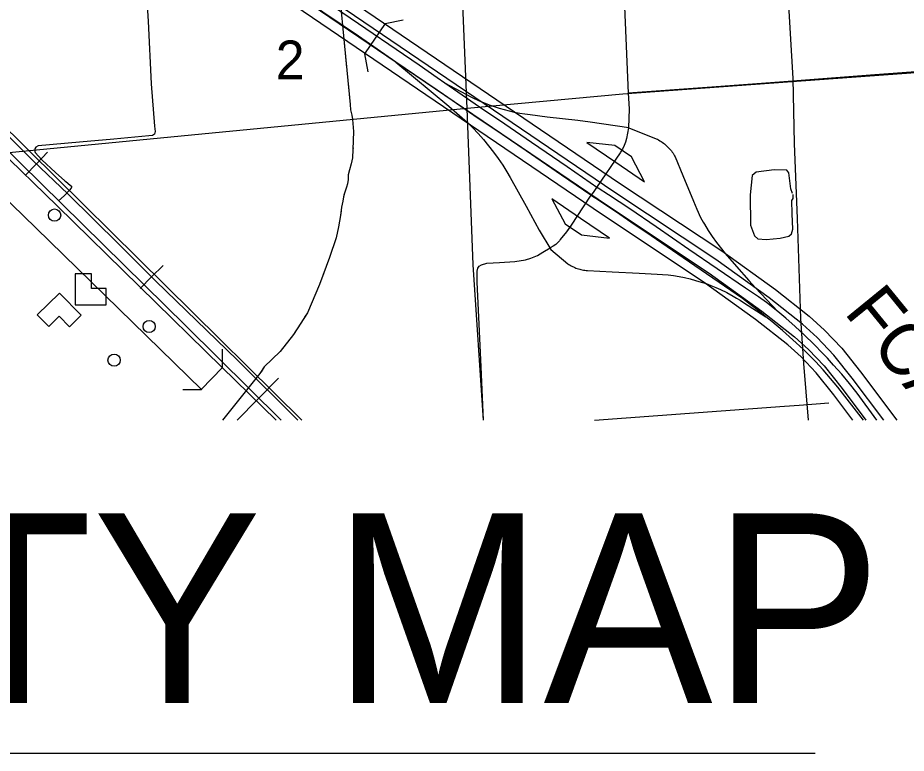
# Model space of a CAD drawing. Extents: x 646058 to 725608, y 1473014 to 1561048.
# Drawn here: x 659024 to 662655, y 1542587 to 1545593 of the extents above; entities that cross this region are included whole.
import ezdxf

# ---------------------------------------------------------------- set-up
doc = ezdxf.new("R2010")
doc.units = 0
doc.layers.add('Default', color=7, linetype='Continuous')
doc.layers.add('R_Grid', color=7, linetype='Continuous')

msp = doc.modelspace()

# ---------------------------------------------------------------- linework, layer by layer
at = {"layer": 'Default'}
for p, q in [((660525.3, 1545570.5), (660441, 1545446.5)), ((660525.3, 1545570.5), (660599, 1545584.6)), ((660441, 1545446.5), (660455.1, 1545372.8)), ((661350, 1545083.4), (661467.9, 1545003.3)), ((661464.8, 1545070.7), (661350, 1545083.4)), ((661531.8, 1545025.2), (661464.8, 1545070.7)), ((659099.7, 1544996.2), (659145.3, 1545043.8)), ((661585.8, 1544923.2), (661531.8, 1545025.2)), ((659099.7, 1544996.2), (659054.1, 1544948.5)), ((661467.9, 1545003.3), (661585.8, 1544923.2)), ((661324.4, 1544773.1), (661206.4, 1544853.2)), ((661206.4, 1544853.2), (661260.5, 1544751.2)), ((661442.3, 1544693), (661324.4, 1544773.1)), ((661260.5, 1544751.2), (661327.5, 1544705.7)), ((661327.5, 1544705.7), (661442.3, 1544693)), ((659570.6, 1544533.8), (659617.3, 1544580.4)), ((659570.6, 1544533.8), (659524, 1544487.1)), ((659860.7, 1544163.5), (659773.2, 1544074.1)), ((659816.9, 1544118.8), (659816.9, 1544118.8)), ((659920.4, 1543949.1), (660089.6, 1544119.9)), ((660043.1, 1544073), (659996.7, 1544026.1))]:
    msp.add_line(p, q, dxfattribs=at)
for points in [[(660769.4, 1545325.6), (660738.5, 1545348.4), (660663.9, 1545400), (660351.8, 1545612.7), (660082.4, 1545798.5), (659708.6, 1546052.2), (659626.2, 1546108.4), (659548.6, 1546163.6), (659466.6, 1546224.7), (659349.1, 1546318.2), (659069.3, 1546541.2), (658623.6, 1546894.9), (658241.6, 1547197.9), (657885.8, 1547482.1), (657634.2, 1547680.9), (657263.8, 1547976.9), (656828.4, 1548315.6), (656441.1, 1548622), (656095.5, 1548896.7), (656046.9, 1548935.5)], [(660769.4, 1545325.6), (660738.5, 1545348.4), (660663.9, 1545400), (660351.8, 1545612.7), (660082.4, 1545798.5), (659708.6, 1546052.2), (659626.2, 1546108.4), (659548.6, 1546163.6), (659466.6, 1546224.7), (659349.1, 1546318.2), (659069.3, 1546541.2), (658623.6, 1546894.9), (658241.6, 1547197.9), (657885.8, 1547482.1), (657634.2, 1547680.9), (657263.8, 1547976.9), (656828.4, 1548315.6), (656441.1, 1548622), (656095.5, 1548896.7), (656046.9, 1548935.5)], [(660769.4, 1545325.6), (660738.5, 1545348.4), (660663.9, 1545400), (660351.8, 1545612.7), (660082.4, 1545798.5), (659708.6, 1546052.2), (659626.2, 1546108.4), (659548.6, 1546163.6), (659466.6, 1546224.7), (659349.1, 1546318.2), (659069.3, 1546541.2), (658623.6, 1546894.9), (658241.6, 1547197.9), (657885.8, 1547482.1), (657634.2, 1547680.9), (657263.8, 1547976.9), (656828.4, 1548315.6), (656441.1, 1548622), (656095.5, 1548896.7), (656046.9, 1548935.5)], [(660769.4, 1545325.6), (660738.5, 1545348.4), (660663.9, 1545400), (660351.8, 1545612.7), (660082.4, 1545798.5), (659708.6, 1546052.2), (659626.2, 1546108.4), (659548.6, 1546163.6), (659466.6, 1546224.7), (659349.1, 1546318.2), (659069.3, 1546541.2), (658623.6, 1546894.9), (658241.6, 1547197.9), (657885.8, 1547482.1), (657634.2, 1547680.9), (657263.8, 1547976.9), (656828.4, 1548315.6), (656441.1, 1548622), (656095.5, 1548896.7), (656046.9, 1548935.5)], [(660568.9, 1545412.2), (660415.9, 1545517.6), (660049.7, 1545765.9), (659676.3, 1546020.4), (659594.4, 1546076.3), (659513.4, 1546133.5), (659434.2, 1546193.4), (659312.7, 1546288.9), (659032.8, 1546511.9), (658586.8, 1546865.8), (658204.4, 1547170.3), (657843.4, 1547456), (657618.6, 1547634.8), (657231.1, 1547944.9), (656803, 1548283.3), (656415.6, 1548589.8), (656070, 1548864.5), (656025.4, 1548900.1)], [(660568.9, 1545412.2), (660415.9, 1545517.6), (660049.7, 1545765.9), (659676.3, 1546020.4), (659594.4, 1546076.3), (659513.4, 1546133.5), (659434.2, 1546193.4), (659312.7, 1546288.9), (659032.8, 1546511.9), (658586.8, 1546865.8), (658204.4, 1547170.3), (657843.4, 1547456), (657618.6, 1547634.8), (657231.1, 1547944.9), (656803, 1548283.3), (656415.6, 1548589.8), (656070, 1548864.5), (656025.4, 1548900.1)], [(660568.9, 1545412.2), (660415.9, 1545517.6), (660049.7, 1545765.9), (659676.3, 1546020.4), (659594.4, 1546076.3), (659513.4, 1546133.5), (659434.2, 1546193.4), (659312.7, 1546288.9), (659032.8, 1546511.9), (658586.8, 1546865.8), (658204.4, 1547170.3), (657843.4, 1547456), (657618.6, 1547634.8), (657231.1, 1547944.9), (656803, 1548283.3), (656415.6, 1548589.8), (656070, 1548864.5), (656025.4, 1548900.1)], [(660568.9, 1545412.2), (660415.9, 1545517.6), (660049.7, 1545765.9), (659676.3, 1546020.4), (659594.4, 1546076.3), (659513.4, 1546133.5), (659434.2, 1546193.4), (659312.7, 1546288.9), (659032.8, 1546511.9), (658586.8, 1546865.8), (658204.4, 1547170.3), (657843.4, 1547456), (657618.6, 1547634.8), (657231.1, 1547944.9), (656803, 1548283.3), (656415.6, 1548589.8), (656070, 1548864.5), (656025.4, 1548900.1)], [(662436.8, 1543949.1), (662359.4, 1544051.8), (662287.7, 1544142), (662226.2, 1544206.7), (662171.1, 1544256.2), (662039.6, 1544360.1), (661825.6, 1544514.5), (661409.9, 1544790.1), (660156.2, 1545642.2), (659402.5, 1546176), (659168.3, 1546365.6), (656047.6, 1548854.7)], [(656121.8, 1548850.2), (659194.9, 1546398.7), (659428.2, 1546209.9), (660180.5, 1545677.1), (661433.6, 1544825.4), (661849.8, 1544549.5), (662065.2, 1544394), (662198.5, 1544288.7), (662255.8, 1544237.2), (662319.7, 1544169.9), (662393, 1544077.8), (662490.1, 1543949.1)], [(662563.6, 1543949.1), (662434.9, 1544119.8), (662359.3, 1544214.8), (662291.6, 1544286.1), (662230.9, 1544340.6), (662094.9, 1544448), (661877.3, 1544605.1), (661459.5, 1544882.1), (660209, 1545732), (659458.9, 1546263.3), (659227.1, 1546450.9), (656233.5, 1548837.4)], [(656290.3, 1548854.7), (659253.7, 1546484), (659484.6, 1546297.2), (660233.2, 1545766.9), (661483.2, 1544917.4)], [(660168.2, 1543949.1), (659919.8, 1544195.1), (659588.3, 1544516.1), (659439.9, 1544664.5), (659227.9, 1544873.5), (659088.6, 1545006.7), (658890.3, 1545205.1), (658596.6, 1545494.3), (658384.6, 1545703.3), (658109.1, 1545971.3), (657900.1, 1546177.3), (657753.3, 1546321.1), (657536.8, 1546533.1), (657293, 1546773.9), (657050.8, 1547016.2), (656776.7, 1547278.1), (656548.1, 1547505.3), (656345.2, 1547702.1), (656118.1, 1547924.7), (656003.1, 1548039), (655996.2, 1548045.9), (655880.4, 1548161), (655686.6, 1548351.8)], [(661399.3, 1548081), (661396.5, 1548033.7), (661404.3, 1547874.9), (661421.1, 1547585.4), (661435.5, 1547270.9), (661451.2, 1546917.6), (661467.5, 1546563.1), (661481.5, 1546210.5), (661490.7, 1545982.8), (661504, 1545638), (661518.1, 1545284.8)], [(661399.3, 1548081), (661396.5, 1548033.7), (661404.3, 1547874.9), (661421.1, 1547585.4), (661435.5, 1547270.9), (661451.2, 1546917.6), (661467.5, 1546563.1), (661481.5, 1546210.5), (661490.7, 1545982.8), (661504, 1545638), (661518.1, 1545284.8)], [(660168.2, 1543949.1), (659919.8, 1544195.1), (659588.3, 1544516.1), (659439.9, 1544664.5), (659227.9, 1544873.5), (659088.6, 1545006.7), (658890.3, 1545205.1), (658596.6, 1545494.3), (658384.6, 1545703.3), (658109.1, 1545971.3), (657900.1, 1546177.3), (657753.3, 1546321.1), (657536.8, 1546533.1), (657293, 1546773.9), (657050.8, 1547016.2), (656776.7, 1547278.1), (656548.1, 1547505.3), (656345.2, 1547702.1), (656118.1, 1547924.7), (656003.1, 1548039)], [(660860.6, 1545222), (660771.9, 1547344.4), (660739.4, 1548040.9)], [(656425.6, 1547675.7), (657430.5, 1546682.8), (658072.2, 1546037.3), (659069.6, 1545049.8)], [(657050.8, 1547016.2), (657293, 1546773.9), (657536.8, 1546533.1), (657753.3, 1546321.1), (657900.1, 1546177.3), (658109.1, 1545971.3), (658384.6, 1545703.3), (658596.6, 1545494.3), (658890.3, 1545205.1), (659088.6, 1545006.7), (659227.9, 1544873.5), (659439.9, 1544664.5), (659588.3, 1544516.1), (659919.8, 1544195.1), (660168.2, 1543949.1)], [(662537, 1546981.5), (662383.9, 1546835.7), (662315.8, 1546767.6), (662283.9, 1546720.8), (662225.4, 1546615.5), (662154.2, 1546481.5), (662139.3, 1546437.9), (662149.9, 1546231.5), (662169.1, 1545738), (662191.4, 1545345.5), (662196.7, 1545079.5), (662209.8, 1544772.2), (662223.4, 1544363.7)], [(656984.6, 1546977.7), (657726.5, 1546250.4), (657872.6, 1546102.8), (658101.1, 1545883.7), (658939.4, 1545061.8), (659185.2, 1544824.5), (659858.4, 1544165.7)], [(659775.5, 1544072), (659098.1, 1544734.9), (658852.2, 1544972.2), (658014.1, 1545794), (657784.9, 1546013.7), (657638.3, 1546161.8), (656924.6, 1546861.4)], [(659538, 1545854.2), (659544.3, 1545769.8), (659556, 1545579.2), (659569.5, 1545323.1), (659582.9, 1545149.7), (659584.7, 1545128.1), (659582.9, 1545117.3), (659574.8, 1545111.9), (659559.6, 1545110.1), (659415.8, 1545097.5), (659276.5, 1545084.9), (659106.7, 1545069.7), (659096.9, 1545063.8), (659093.3, 1545056.9), (659093.3, 1545048.5), (659093.7, 1545046.5)], [(660332.6, 1545762.5), (660359.6, 1545477.6), (660381.7, 1545239.3), (660384.1, 1545217.2), (660389, 1545195.1), (660391.5, 1545177.9), (660396.4, 1545128.8), (660393.9, 1545055.1), (660391.5, 1545020.7), (660386.6, 1544996.2), (660379.2, 1544971.6), (660374.3, 1544951.9), (660374.3, 1544932.3), (660371.8, 1544915.1), (660366.9, 1544900.4), (660359.6, 1544875.8), (660354.7, 1544861.1), (660352.2, 1544843.9), (660347.3, 1544819.3), (660342.4, 1544784.9), (660335, 1544738.2), (660325.2, 1544694), (660298.2, 1544613), (660256.4, 1544502.4), (660207.3, 1544387), (660150.8, 1544298.6), (660096.8, 1544229.8)], [(660358.5, 1545488.5), (660359.6, 1545477.6), (660381.7, 1545239.3), (660384.1, 1545217.2), (660389, 1545195.1), (660391.5, 1545177.9), (660396.4, 1545128.8), (660393.9, 1545055.1), (660391.5, 1545020.7), (660386.6, 1544996.2), (660379.2, 1544971.6), (660374.3, 1544951.9), (660374.3, 1544932.3), (660371.8, 1544915.1), (660366.9, 1544900.4), (660359.6, 1544875.8), (660354.7, 1544861.1), (660352.2, 1544843.9), (660347.3, 1544819.3), (660342.4, 1544784.9), (660335, 1544738.2), (660325.2, 1544694), (660298.2, 1544613), (660256.4, 1544502.4), (660207.3, 1544387), (660150.8, 1544298.6), (660096.8, 1544229.8)], [(660358.5, 1545488.5), (660359.6, 1545477.6), (660367.7, 1545389.9)], [(663515.5, 1545427.8), (661496.4, 1545281.1), (660860.6, 1545222)], [(663516, 1545434.5), (663487, 1545431.9), (663421.4, 1545421.1), (663230.3, 1545411.1), (662991.1, 1545394.5), (662527.5, 1545359.6), (662137.9, 1545329.7), (661841.3, 1545308.9), (661518.1, 1545284.8)], [(663487, 1545431.9), (663421.4, 1545421.1), (663230.3, 1545411.1), (662991.1, 1545394.5), (662527.5, 1545359.6), (662137.9, 1545329.7), (661841.3, 1545308.9), (661518.1, 1545284.8)], [(660568.9, 1545412.2), (660785, 1545232), (660818.6, 1545203.7), (660851.4, 1545174.4), (660883.2, 1545144), (660905.6, 1545120.1), (660927.3, 1545095.5), (660948.2, 1545070.3), (660968.2, 1545044.4), (660987.5, 1545017.9), (661005.9, 1544990.8), (661023.4, 1544963.2), (661036.7, 1544940.2), (661101.2, 1544823.2), (661155.4, 1544724.7), (661203, 1544646.4)], [(662082.1, 1544371.1), (662062.5, 1544387.1), (662017.6, 1544421.8), (661985.6, 1544445.6), (661743.4, 1544612.1), (661591.1, 1544716.4), (661543.4, 1544748.6), (661484.3, 1544788.8), (661415.7, 1544835.3), (661397, 1544847.2), (661379.8, 1544858.1), (661372.5, 1544863.1), (661365.8, 1544867.8), (661246.8, 1544950.5), (661101.1, 1545049.7), (660969.7, 1545138.8), (660905.9, 1545182.2), (660834.6, 1545230.4), (660746.1, 1545291.8), (660737.3, 1545297.9), (660645.5, 1545359.5), (660568.9, 1545412.2)], [(662082.1, 1544371.1), (662062.5, 1544387.1), (662017.6, 1544421.8), (661985.6, 1544445.6), (661743.4, 1544612.1), (661591.1, 1544716.4), (661543.4, 1544748.6), (661484.3, 1544788.8), (661415.7, 1544835.3), (661397, 1544847.2), (661379.8, 1544858.1), (661372.5, 1544863.1), (661365.8, 1544867.8), (661246.8, 1544950.5), (661101.1, 1545049.7), (660969.7, 1545138.8), (660905.9, 1545182.2), (660834.6, 1545230.4), (660746.1, 1545291.8), (660737.3, 1545297.9), (660645.5, 1545359.5), (660568.9, 1545412.2)], [(662082.1, 1544371.1), (662062.5, 1544387.1), (662017.6, 1544421.8), (661985.6, 1544445.6), (661743.4, 1544612.1), (661591.1, 1544716.4), (661543.4, 1544748.6), (661484.3, 1544788.8), (661415.7, 1544835.3), (661397, 1544847.2), (661379.8, 1544858.1), (661372.5, 1544863.1), (661365.8, 1544867.8), (661246.8, 1544950.5), (661101.1, 1545049.7), (660969.7, 1545138.8), (660905.9, 1545182.2), (660834.6, 1545230.4), (660746.1, 1545291.8), (660737.3, 1545297.9), (660645.5, 1545359.5), (660568.9, 1545412.2)], [(662082.1, 1544371.1), (662062.5, 1544387.1), (662017.6, 1544421.8), (661985.6, 1544445.6), (661743.4, 1544612.1), (661591.1, 1544716.4), (661543.4, 1544748.6), (661484.3, 1544788.8), (661415.7, 1544835.3), (661397, 1544847.2), (661379.8, 1544858.1), (661372.5, 1544863.1), (661365.8, 1544867.8), (661246.8, 1544950.5), (661101.1, 1545049.7), (660969.7, 1545138.8), (660905.9, 1545182.2), (660834.6, 1545230.4), (660746.1, 1545291.8), (660737.3, 1545297.9), (660645.5, 1545359.5), (660568.9, 1545412.2)], [(660373.8, 1545324.2), (660381.7, 1545239.3), (660384.1, 1545217.2), (660389, 1545195.1), (660391.5, 1545177.9), (660396.4, 1545128.8), (660396.4, 1545127.6)], [(661521.2, 1545143.7), (661362.9, 1545166.5), (661312.3, 1545172.9), (661187.6, 1545187.5), (661117.6, 1545196.2), (661096.6, 1545198.8), (661075.6, 1545202.1), (661054.7, 1545206.1), (661034.1, 1545210.9), (661013.5, 1545216.3), (660993.2, 1545222.4), (660956.4, 1545234.7), (660911.6, 1545253), (660880, 1545268), (660769.4, 1545325.6)], [(662130.6, 1544392.1), (662083.5, 1544428.9), (662051.7, 1544452.4), (661998.6, 1544488.1), (661766.6, 1544646), (661632.7, 1544739), (661525.8, 1544811.6), (661438.2, 1544869.7), (661395.7, 1544897.1), (661395.3, 1544897.4), (661270, 1544984.4), (661124.1, 1545083.7), (660992.7, 1545172.8), (660928.9, 1545216.2), (660857.8, 1545264.4), (660769.4, 1545325.6)], [(662130.6, 1544392.1), (662083.5, 1544428.9), (662051.7, 1544452.4), (661998.6, 1544488.1), (661766.6, 1544646), (661632.7, 1544739), (661525.8, 1544811.6), (661438.2, 1544869.7), (661395.7, 1544897.1), (661395.3, 1544897.4), (661270, 1544984.4), (661124.1, 1545083.7), (660992.7, 1545172.8), (660928.9, 1545216.2), (660857.8, 1545264.4), (660769.4, 1545325.6)], [(662130.6, 1544392.1), (662083.5, 1544428.9), (662051.7, 1544452.4), (661998.6, 1544488.1), (661766.6, 1544646), (661632.7, 1544739), (661525.8, 1544811.6), (661438.2, 1544869.7), (661395.7, 1544897.1), (661395.3, 1544897.4), (661270, 1544984.4), (661124.1, 1545083.7), (660992.7, 1545172.8), (660928.9, 1545216.2), (660857.8, 1545264.4), (660769.4, 1545325.6)], [(662130.6, 1544392.1), (662083.5, 1544428.9), (662051.7, 1544452.4), (661998.6, 1544488.1), (661766.6, 1544646), (661632.7, 1544739), (661525.8, 1544811.6), (661438.2, 1544869.7), (661395.7, 1544897.1), (661395.3, 1544897.4), (661270, 1544984.4), (661124.1, 1545083.7), (660992.7, 1545172.8), (660928.9, 1545216.2), (660857.8, 1545264.4), (660769.4, 1545325.6)], [(661518.1, 1545284.8), (661522.3, 1545220.8), (661520.4, 1545143.8)], [(661518.1, 1545284.8), (661522.3, 1545220.8), (661520.4, 1545143.8)], [(660860.6, 1545222), (658930.3, 1545036.4), (658107.4, 1544984.1)], [(660927.4, 1543949.1), (660885, 1544583.7), (660860.6, 1545222)], [(661520.4, 1545143.8), (661512.4, 1545100.4), (661508.1, 1545085.4), (661502.6, 1545070.9), (661495.9, 1545056.8), (661488, 1545043.4), (661486.4, 1545040.9), (661389.8, 1544899.1), (661376.3, 1544878.6), (661363.9, 1544863.6), (661308.7, 1544781.6), (661288.9, 1544749.6), (661266.8, 1544717.8), (661241.3, 1544686.4), (661237.7, 1544682.1), (661234.1, 1544678), (661223.2, 1544666.8), (661212.1, 1544660.2), (661199.3, 1544652.5)], [(661520.4, 1545143.8), (661512.4, 1545100.4), (661508.1, 1545085.4), (661502.6, 1545070.9), (661495.9, 1545056.8), (661491.5, 1545049.2)], [(661521.2, 1545143.7), (661632.9, 1545098.9), (661638.1, 1545096.4), (661643.2, 1545093.7), (661648.2, 1545090.8), (661653.1, 1545087.7), (661657.9, 1545084.5), (661662.6, 1545081.1), (661667.2, 1545077.6), (661671.6, 1545073.9), (661675.9, 1545070), (661680.1, 1545066), (661684.1, 1545061.9), (661688, 1545057.6), (661691.7, 1545053.2), (661695.3, 1545048.7), (661698.7, 1545044), (661702, 1545039.2), (661705, 1545034.3), (661707.9, 1545029.3), (661710.7, 1545024.2), (661742.6, 1544947.9), (661785.7, 1544844.2), (661800, 1544810.5), (661815, 1544777.2), (661825.8, 1544757.2), (661830.1, 1544749.7), (661845.9, 1544723.9), (661862.6, 1544698.7), (661880.1, 1544674), (661915.5, 1544629.8), (661961.4, 1544576.9), (662012.1, 1544519.9), (662038.7, 1544489.8), (662130.6, 1544392.1)], [(658948.3, 1545082.3), (659710.5, 1544334.3), (660100.4, 1543949.1)], [(658948.3, 1545082.3), (659710.5, 1544334.3), (660100.4, 1543949.1)], [(658948.3, 1545082.3), (659710.5, 1544334.3), (660100.4, 1543949.1)], [(658948.3, 1545082.3), (659710.5, 1544334.3), (660100.4, 1543949.1)], [(660394.2, 1545061.7), (660393.9, 1545055.1), (660391.5, 1545020.7), (660386.6, 1544996.2), (660379.2, 1544971.6), (660374.3, 1544951.9), (660374.3, 1544932.3), (660371.8, 1544915.1), (660366.9, 1544900.4), (660359.6, 1544875.8), (660357.1, 1544868.4)], [(659069.6, 1545049.8), (660185.2, 1543949.1)], [(659093.7, 1545046.5), (659094.5, 1545042.4), (659121.9, 1545013.1), (659177.3, 1544960.4), (659216, 1544926.8)], [(662190.7, 1544874.3), (662183.9, 1544894.3), (662176.1, 1544959.5), (662167.3, 1544970.2), (662115.8, 1544972.1), (662041.8, 1544961.9), (662025.7, 1544948.8), (662018, 1544869.4), (662018.4, 1544745.8), (662035, 1544701.5), (662049.1, 1544689.4), (662082.7, 1544687.4), (662140.6, 1544692.8), (662176.1, 1544701), (662186.3, 1544709.8), (662191.7, 1544728.8), (662189.7, 1544792), (662187.3, 1544846.1), (662193.6, 1544853.9), (662192.6, 1544870.9)], [(659216, 1544926.8), (659219.9, 1544923.4), (659237.6, 1544909), (659243.2, 1544904.5), (659243.7, 1544901.7), (659243.2, 1544900.2)], [(661483.2, 1544917.4), (661901.5, 1544640.1), (662120.5, 1544482), (662258.3, 1544373.2), (662321.3, 1544316.5), (662391.4, 1544242.7), (662468.5, 1544145.9), (662616.8, 1543949.1)], [(659243.2, 1544900.2), (659241.7, 1544896.3), (659233.6, 1544887.2), (659213, 1544865.9), (659190.6, 1544844.8)], [(660345, 1544803.6), (660342.4, 1544784.9), (660335, 1544738.2), (660325.2, 1544694), (660298.2, 1544613), (660297.8, 1544611.9)], [(661284.5, 1544743.3), (661266.8, 1544717.8), (661241.3, 1544686.4), (661237.7, 1544682.1), (661234.1, 1544678), (661223.2, 1544666.8), (661212.1, 1544660.2), (661199.3, 1544652.5)], [(660927.4, 1543949.1), (660917.9, 1544166.9), (660909.5, 1544340.9), (660901.1, 1544512.2), (660901.1, 1544558.1), (660904.3, 1544569.1), (660910.2, 1544577.5), (660919.2, 1544583.3), (660941.2, 1544589.8), (660992.9, 1544592.4), (661055.6, 1544597.6), (661098.9, 1544603.4), (661120.3, 1544610.5), (661148.7, 1544622.1), (661170, 1544635.7), (661199.3, 1544652.5)], [(660927.4, 1543949.1), (660917.9, 1544166.9), (660909.5, 1544340.9), (660901.1, 1544512.2), (660901.1, 1544558.1), (660904.3, 1544569.1), (660910.2, 1544577.5), (660919.2, 1544583.3), (660941.2, 1544589.8), (660992.9, 1544592.4), (661055.6, 1544597.6), (661098.9, 1544603.4), (661120.3, 1544610.5), (661148.7, 1544622.1), (661170, 1544635.7), (661199.3, 1544652.5)], [(661203, 1544646.4), (661272.2, 1544587.9), (661276.7, 1544584.9), (661281.2, 1544582.1), (661285.9, 1544579.4), (661290.6, 1544576.9), (661295.4, 1544574.6), (661300.3, 1544572.4), (661305.3, 1544570.4), (661310.3, 1544568.5), (661315.4, 1544566.9), (661320.6, 1544565.4), (661325.8, 1544564.1), (661331, 1544562.9), (661336.3, 1544562), (661341.6, 1544561.2), (661346.9, 1544560.6), (661352.3, 1544560.2), (661453.6, 1544555.2), (661563.2, 1544549.6), (661637.3, 1544545.9), (661659.7, 1544544.4), (661682.2, 1544542.2), (661704.5, 1544539.3), (661726.7, 1544535.6), (661748.9, 1544531.2), (661771.8, 1544525.9), (661794.5, 1544519.9), (661817.1, 1544513.2), (661837.1, 1544506.6), (661856.9, 1544499.3), (661876.4, 1544491.3), (661895.6, 1544482.6), (661921.8, 1544469.7), (661947.5, 1544455.8), (661961.8, 1544447.5), (661975.9, 1544438.8), (661989.8, 1544429.7), (662082.1, 1544371.1)], [(660274.5, 1544550.2), (660256.4, 1544502.4), (660207.3, 1544387), (660195.7, 1544368.9)], [(662481.3, 1543949.1), (662375.7, 1544083.7), (662346.2, 1544119.2), (662315.7, 1544153.8), (662284.2, 1544187.6), (662251.7, 1544220.4), (662240.6, 1544231.3), (662233.6, 1544238), (662192.1, 1544276.8), (662149.7, 1544314.5), (662106.5, 1544351.3), (662082.1, 1544371.1)], [(662481.3, 1543949.1), (662375.7, 1544083.7), (662346.2, 1544119.2), (662315.7, 1544153.8), (662284.2, 1544187.6), (662251.7, 1544220.4), (662240.6, 1544231.3), (662233.6, 1544238), (662192.1, 1544276.8), (662149.7, 1544314.5), (662106.5, 1544351.3), (662082.1, 1544371.1)], [(662481.3, 1543949.1), (662375.7, 1544083.7), (662346.2, 1544119.2), (662315.7, 1544153.8), (662284.2, 1544187.6), (662251.7, 1544220.4), (662240.6, 1544231.3), (662233.6, 1544238), (662192.1, 1544276.8), (662149.7, 1544314.5), (662106.5, 1544351.3), (662082.1, 1544371.1)], [(662481.3, 1543949.1), (662375.7, 1544083.7), (662346.2, 1544119.2), (662315.7, 1544153.8), (662284.2, 1544187.6), (662251.7, 1544220.4), (662240.6, 1544231.3), (662233.6, 1544238), (662192.1, 1544276.8), (662149.7, 1544314.5), (662106.5, 1544351.3), (662082.1, 1544371.1)], [(662535.6, 1543949.1), (662454.2, 1544058.4), (662423.3, 1544097.7), (662391.4, 1544136.2), (662358.5, 1544173.8), (662333, 1544201.5), (662314.9, 1544220.7), (662277.7, 1544258.5), (662239.6, 1544295.3), (662200.7, 1544331.2), (662162.6, 1544364.7), (662130.6, 1544392.1)], [(662535.6, 1543949.1), (662454.2, 1544058.4), (662423.3, 1544097.7), (662391.4, 1544136.2), (662358.5, 1544173.8), (662333, 1544201.5), (662314.9, 1544220.7), (662277.7, 1544258.5), (662239.6, 1544295.3), (662200.7, 1544331.2), (662162.6, 1544364.7), (662130.6, 1544392.1)], [(662535.6, 1543949.1), (662454.2, 1544058.4), (662423.3, 1544097.7), (662391.4, 1544136.2), (662358.5, 1544173.8), (662333, 1544201.5), (662314.9, 1544220.7), (662277.7, 1544258.5), (662239.6, 1544295.3), (662200.7, 1544331.2), (662162.6, 1544364.7), (662130.6, 1544392.1)], [(662535.6, 1543949.1), (662454.2, 1544058.4), (662423.3, 1544097.7), (662391.4, 1544136.2), (662358.5, 1544173.8), (662333, 1544201.5), (662314.9, 1544220.7), (662277.7, 1544258.5), (662239.6, 1544295.3), (662200.7, 1544331.2), (662162.6, 1544364.7), (662130.6, 1544392.1)], [(662223.4, 1544363.7), (662235.4, 1544180.5), (662254.3, 1543949.1)], [(660160.2, 1544313.2), (660150.8, 1544298.6), (660096.8, 1544229.8), (660030.5, 1544165.9), (660029.9, 1544165)], [(659860.7, 1544163.5), (659859.9, 1544238.5)], [(660096.8, 1544229.8), (660030.5, 1544165.9), (660013.3, 1544138.9), (659860.4, 1543949.1)], [(660096.8, 1544229.8), (660030.5, 1544165.9), (660017.9, 1544146.1)], [(659858.4, 1544165.7), (660079.7, 1543949.1)], [(659698.2, 1544073.3), (659773.2, 1544074.1)], [(661381.7, 1543949.1), (662157.9, 1544005.9), (662218, 1544010.4), (662338.9, 1544018.8)], [(661381.7, 1543949.1), (662157.9, 1544005.9), (662218, 1544010.4), (662338.9, 1544018.8)]]:
    msp.add_lwpolyline(points, dxfattribs=at)
for points in [[(659258.4, 1544420), (659385.5, 1544420), (659385.5, 1544487), (659325.4, 1544487), (659325.4, 1544547), (659258.4, 1544547)], [(659194.2, 1544468.2), (659103.5, 1544379.3), (659150.4, 1544331.4), (659193.3, 1544373.5), (659235.3, 1544330.6), (659283.1, 1544377.4)]]:
    msp.add_lwpolyline(points, close=True, dxfattribs=at)
for centre in [(659174.2, 1544786.8), (659560.8, 1544331.2), (659417.2, 1544193.9)]:
    msp.add_circle(centre, 25, dxfattribs=at)
at = {"layer": 'R_Grid'}
msp.add_line((655384.9, 1542587), (662283, 1542587), dxfattribs=at)

# ---------------------------------------------------------------- texts
at = {"layer": 'Default'}
msp.add_text('2', height=158.4, dxfattribs=at).set_placement((660078.2, 1545341.8))
msp.add_text('FCA', height=211.2, rotation=309.2036, dxfattribs=at).set_placement((662397.7, 1544388.1))
at = {"layer": 'R_Grid'}
msp.add_text('VICINITY MAP', height=775.249, dxfattribs=at).set_placement((655643.4, 1542792.4))

doc.saveas('drawing.dxf')
